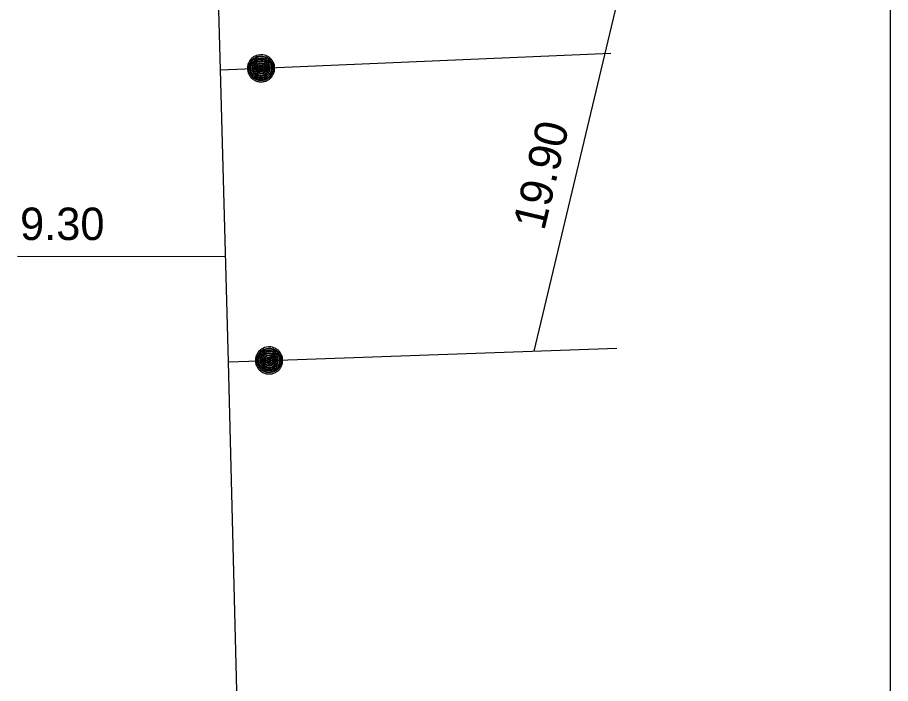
# Model space of a CAD drawing. Extents: x -820257 to -819974, y -1070894 to -1070484.
# Drawn here: x -820007.89 to -819975.6, y -1070794.86 to -1070770.22 of the extents above; entities that cross this region are included whole.
import ezdxf

# ---------------------------------------------------------------- set-up
doc = ezdxf.new("R2010")
doc.units = 0
for name, color, linetype in [('Default', 7, 'Continuous'), ('Oměrka vodovodu', 7, 'Continuous'), ('Oměrka-text', 7, 'Continuous'), ('Přípojka vodovodu', 7, 'Continuous'), ('Přípojkový uzávěr', 7, 'Continuous'), ('Roz-řad', 7, 'Continuous')]:
    doc.layers.add(name, color=color, linetype=linetype)

msp = doc.modelspace()

# ---------------------------------------------------------------- linework, layer by layer
at = {"layer": 'Default'}
msp.add_line((-819975.603, -1070893.932), (-819975.603, -1070484.403), dxfattribs=at)
at = {"layer": 'Oměrka vodovodu'}
for p, q in [((-819988.777, -1070782.56), (-819983.571, -1070760.651)), ((-820007.891, -1070779.053), (-820000.192, -1070779.056))]:
    msp.add_line(p, q, dxfattribs=at)
at = {"layer": 'Přípojka vodovodu'}
for points in [[(-820000.381, -1070772.161), (-819998.882, -1070772.096), (-819985.943, -1070771.539)], [(-820000.085, -1070782.958), (-819998.586, -1070782.905), (-819985.727, -1070782.453)]]:
    msp.add_lwpolyline(points, dxfattribs=at)
at = {"layer": 'Přípojkový uzávěr'}
for points in [[(-819998.904, -1070771.597), (-819998.778, -1070771.592), (-819998.656, -1070771.651), (-819998.534, -1070771.711), (-819998.461, -1070771.828), (-819998.388, -1070771.945), (-819998.382, -1070772.076), (-819998.377, -1070772.206), (-819998.438, -1070772.327), (-819998.498, -1070772.449), (-819998.615, -1070772.52), (-819998.731, -1070772.591), (-819998.861, -1070772.597), (-819998.99, -1070772.602), (-819999.112, -1070772.541), (-819999.234, -1070772.481), (-819999.305, -1070772.365), (-819999.376, -1070772.249), (-819999.381, -1070772.119), (-819999.387, -1070771.988), (-819999.325, -1070771.865), (-819999.263, -1070771.742), (-819999.147, -1070771.672), (-819999.03, -1070771.603), (-819998.904, -1070771.597)], [(-819998.902, -1070771.644), (-819999.016, -1070771.649), (-819999.122, -1070771.712), (-819999.228, -1070771.775), (-819999.284, -1070771.887), (-819999.34, -1070771.998), (-819999.335, -1070772.117), (-819999.33, -1070772.235), (-819999.265, -1070772.34), (-819999.201, -1070772.445), (-819999.091, -1070772.5), (-819998.98, -1070772.555), (-819998.863, -1070772.55), (-819998.745, -1070772.545), (-819998.639, -1070772.48), (-819998.534, -1070772.416), (-819998.479, -1070772.306), (-819998.424, -1070772.196), (-819998.429, -1070772.078), (-819998.434, -1070771.959), (-819998.501, -1070771.853), (-819998.567, -1070771.747), (-819998.677, -1070771.693), (-819998.788, -1070771.639), (-819998.902, -1070771.644)], [(-819998.9, -1070771.678), (-819998.795, -1070771.674), (-819998.693, -1070771.723), (-819998.59, -1070771.773), (-819998.529, -1070771.871), (-819998.468, -1070771.97), (-819998.463, -1070772.079), (-819998.459, -1070772.188), (-819998.509, -1070772.29), (-819998.56, -1070772.392), (-819998.658, -1070772.451), (-819998.755, -1070772.511), (-819998.864, -1070772.516), (-819998.973, -1070772.52), (-819999.075, -1070772.469), (-819999.177, -1070772.419), (-819999.237, -1070772.321), (-819999.296, -1070772.224), (-819999.301, -1070772.115), (-819999.305, -1070772.006), (-819999.253, -1070771.903), (-819999.202, -1070771.799), (-819999.104, -1070771.741), (-819999.006, -1070771.683), (-819998.9, -1070771.678)], [(-819998.899, -1070771.722), (-819999.055, -1070771.729), (-819999.159, -1070771.844), (-819999.263, -1070771.958), (-819999.257, -1070772.114), (-819999.25, -1070772.269), (-819999.135, -1070772.373), (-819999.021, -1070772.478), (-819998.867, -1070772.472), (-819998.711, -1070772.465), (-819998.606, -1070772.351), (-819998.501, -1070772.236), (-819998.507, -1070772.081), (-819998.514, -1070771.926), (-819998.628, -1070771.821), (-819998.742, -1070771.716), (-819998.899, -1070771.722)], [(-819998.897, -1070771.768), (-819998.76, -1070771.762), (-819998.661, -1070771.854), (-819998.561, -1070771.946), (-819998.555, -1070772.082), (-819998.549, -1070772.218), (-819998.641, -1070772.318), (-819998.733, -1070772.418), (-819998.869, -1070772.424), (-819999.005, -1070772.43), (-819999.105, -1070772.338), (-819999.205, -1070772.246), (-819999.211, -1070772.11), (-819999.217, -1070771.974), (-819999.125, -1070771.874), (-819999.034, -1070771.774), (-819998.897, -1070771.768)], [(-819998.895, -1070771.808), (-819999.015, -1070771.813), (-819999.096, -1070771.901), (-819999.176, -1070771.989), (-819999.171, -1070772.108), (-819999.166, -1070772.228), (-819999.078, -1070772.309), (-819998.991, -1070772.389), (-819998.871, -1070772.384), (-819998.751, -1070772.379), (-819998.67, -1070772.291), (-819998.59, -1070772.203), (-819998.595, -1070772.084), (-819998.6, -1070771.964), (-819998.687, -1070771.883), (-819998.775, -1070771.803), (-819998.895, -1070771.808)], [(-819998.893, -1070771.847), (-819998.788, -1070771.843), (-819998.713, -1070771.913), (-819998.637, -1070771.983), (-819998.632, -1070772.087), (-819998.628, -1070772.19), (-819998.698, -1070772.266), (-819998.768, -1070772.342), (-819998.872, -1070772.347), (-819998.975, -1070772.351), (-819999.051, -1070772.281), (-819999.127, -1070772.212), (-819999.132, -1070772.108), (-819999.136, -1070772.004), (-819999.067, -1070771.928), (-819998.998, -1070771.852), (-819998.893, -1070771.847)], [(-819998.891, -1070771.894), (-819998.976, -1070771.897), (-819999.032, -1070771.959), (-819999.089, -1070772.021), (-819999.085, -1070772.105), (-819999.082, -1070772.19), (-819999.02, -1070772.246), (-819998.958, -1070772.303), (-819998.874, -1070772.299), (-819998.79, -1070772.296), (-819998.733, -1070772.234), (-819998.676, -1070772.172), (-819998.68, -1070772.088), (-819998.683, -1070772.003), (-819998.745, -1070771.947), (-819998.807, -1070771.89), (-819998.891, -1070771.894)], [(-819998.89, -1070771.928), (-819998.819, -1070771.925), (-819998.768, -1070771.972), (-819998.717, -1070772.019), (-819998.714, -1070772.089), (-819998.711, -1070772.159), (-819998.758, -1070772.211), (-819998.805, -1070772.262), (-819998.875, -1070772.265), (-819998.945, -1070772.268), (-819998.997, -1070772.221), (-819999.048, -1070772.174), (-819999.051, -1070772.104), (-819999.054, -1070772.033), (-819999.007, -1070771.982), (-819998.96, -1070771.931), (-819998.89, -1070771.928)], [(-819998.888, -1070771.972), (-819998.94, -1070771.974), (-819998.974, -1070772.012), (-819999.009, -1070772.051), (-819999.007, -1070772.102), (-819999.005, -1070772.154), (-819998.966, -1070772.189), (-819998.928, -1070772.224), (-819998.877, -1070772.222), (-819998.825, -1070772.22), (-819998.79, -1070772.181), (-819998.755, -1070772.143), (-819998.757, -1070772.092), (-819998.759, -1070772.04), (-819998.797, -1070772.005), (-819998.835, -1070771.97), (-819998.888, -1070771.972)], [(-819998.886, -1070772.019), (-819998.853, -1070772.017), (-819998.829, -1070772.039), (-819998.806, -1070772.06), (-819998.804, -1070772.094), (-819998.803, -1070772.126), (-819998.824, -1070772.15), (-819998.846, -1070772.174), (-819998.879, -1070772.175), (-819998.911, -1070772.176), (-819998.935, -1070772.154), (-819998.959, -1070772.133), (-819998.961, -1070772.1), (-819998.962, -1070772.067), (-819998.94, -1070772.044), (-819998.918, -1070772.02), (-819998.886, -1070772.019)], [(-819998.884, -1070772.05), (-819998.904, -1070772.051), (-819998.917, -1070772.065), (-819998.93, -1070772.079), (-819998.929, -1070772.099), (-819998.928, -1070772.119), (-819998.914, -1070772.132), (-819998.9, -1070772.145), (-819998.88, -1070772.144), (-819998.86, -1070772.143), (-819998.848, -1070772.129), (-819998.835, -1070772.114), (-819998.836, -1070772.095), (-819998.836, -1070772.075), (-819998.85, -1070772.062), (-819998.864, -1070772.049), (-819998.884, -1070772.05)], [(-819998.604, -1070782.405), (-819998.478, -1070782.401), (-819998.356, -1070782.461), (-819998.234, -1070782.521), (-819998.163, -1070782.639), (-819998.091, -1070782.757), (-819998.086, -1070782.888), (-819998.082, -1070783.017), (-819998.143, -1070783.139), (-819998.205, -1070783.26), (-819998.322, -1070783.33), (-819998.439, -1070783.4), (-819998.569, -1070783.404), (-819998.698, -1070783.409), (-819998.819, -1070783.347), (-819998.941, -1070783.286), (-819999.011, -1070783.169), (-819999.081, -1070783.053), (-819999.086, -1070782.923), (-819999.09, -1070782.792), (-819999.027, -1070782.669), (-819998.964, -1070782.547), (-819998.847, -1070782.478), (-819998.73, -1070782.41), (-819998.604, -1070782.405)], [(-819998.602, -1070782.452), (-819998.716, -1070782.456), (-819998.823, -1070782.518), (-819998.929, -1070782.58), (-819998.986, -1070782.691), (-819999.043, -1070782.803), (-819999.039, -1070782.921), (-819999.035, -1070783.039), (-819998.971, -1070783.144), (-819998.908, -1070783.25), (-819998.798, -1070783.306), (-819998.688, -1070783.362), (-819998.57, -1070783.358), (-819998.452, -1070783.353), (-819998.346, -1070783.29), (-819998.24, -1070783.226), (-819998.185, -1070783.117), (-819998.129, -1070783.007), (-819998.133, -1070782.889), (-819998.137, -1070782.771), (-819998.203, -1070782.664), (-819998.268, -1070782.557), (-819998.378, -1070782.502), (-819998.488, -1070782.448), (-819998.602, -1070782.452)], [(-819998.601, -1070782.486), (-819998.495, -1070782.482), (-819998.394, -1070782.533), (-819998.292, -1070782.583), (-819998.231, -1070782.682), (-819998.171, -1070782.781), (-819998.167, -1070782.89), (-819998.163, -1070782.999), (-819998.215, -1070783.101), (-819998.266, -1070783.202), (-819998.364, -1070783.261), (-819998.462, -1070783.32), (-819998.572, -1070783.323), (-819998.68, -1070783.327), (-819998.782, -1070783.276), (-819998.884, -1070783.224), (-819998.942, -1070783.126), (-819999.001, -1070783.029), (-819999.005, -1070782.92), (-819999.008, -1070782.81), (-819998.956, -1070782.707), (-819998.903, -1070782.605), (-819998.805, -1070782.547), (-819998.707, -1070782.49), (-819998.601, -1070782.486)], [(-819998.6, -1070782.53), (-819998.756, -1070782.535), (-819998.861, -1070782.649), (-819998.966, -1070782.763), (-819998.961, -1070782.918), (-819998.955, -1070783.074), (-819998.842, -1070783.179), (-819998.728, -1070783.285), (-819998.574, -1070783.28), (-819998.418, -1070783.274), (-819998.312, -1070783.161), (-819998.206, -1070783.047), (-819998.211, -1070782.892), (-819998.217, -1070782.736), (-819998.33, -1070782.63), (-819998.442, -1070782.524), (-819998.6, -1070782.53)], [(-819998.598, -1070782.576), (-819998.461, -1070782.571), (-819998.363, -1070782.664), (-819998.264, -1070782.756), (-819998.259, -1070782.892), (-819998.254, -1070783.028), (-819998.347, -1070783.128), (-819998.439, -1070783.227), (-819998.575, -1070783.232), (-819998.712, -1070783.237), (-819998.811, -1070783.144), (-819998.91, -1070783.051), (-819998.915, -1070782.915), (-819998.92, -1070782.779), (-819998.827, -1070782.68), (-819998.735, -1070782.581), (-819998.598, -1070782.576)], [(-819998.597, -1070782.615), (-819998.717, -1070782.62), (-819998.798, -1070782.707), (-819998.879, -1070782.794), (-819998.875, -1070782.914), (-819998.871, -1070783.033), (-819998.784, -1070783.115), (-819998.697, -1070783.196), (-819998.577, -1070783.192), (-819998.457, -1070783.188), (-819998.376, -1070783.101), (-819998.294, -1070783.013), (-819998.299, -1070782.894), (-819998.303, -1070782.774), (-819998.39, -1070782.693), (-819998.477, -1070782.611), (-819998.597, -1070782.615)], [(-819998.595, -1070782.655), (-819998.49, -1070782.651), (-819998.415, -1070782.722), (-819998.34, -1070782.792), (-819998.336, -1070782.896), (-819998.332, -1070783), (-819998.403, -1070783.075), (-819998.474, -1070783.151), (-819998.578, -1070783.155), (-819998.681, -1070783.158), (-819998.756, -1070783.088), (-819998.832, -1070783.017), (-819998.836, -1070782.914), (-819998.839, -1070782.81), (-819998.769, -1070782.734), (-819998.7, -1070782.659), (-819998.595, -1070782.655)], [(-819998.594, -1070782.701), (-819998.678, -1070782.704), (-819998.735, -1070782.766), (-819998.792, -1070782.827), (-819998.789, -1070782.911), (-819998.786, -1070782.996), (-819998.725, -1070783.053), (-819998.664, -1070783.11), (-819998.579, -1070783.107), (-819998.495, -1070783.104), (-819998.438, -1070783.043), (-819998.38, -1070782.982), (-819998.383, -1070782.897), (-819998.386, -1070782.813), (-819998.448, -1070782.756), (-819998.509, -1070782.698), (-819998.594, -1070782.701)], [(-819998.592, -1070782.736), (-819998.522, -1070782.733), (-819998.471, -1070782.781), (-819998.421, -1070782.828), (-819998.418, -1070782.898), (-819998.416, -1070782.969), (-819998.463, -1070783.019), (-819998.511, -1070783.07), (-819998.58, -1070783.073), (-819998.651, -1070783.075), (-819998.702, -1070783.028), (-819998.752, -1070782.98), (-819998.755, -1070782.91), (-819998.757, -1070782.84), (-819998.71, -1070782.789), (-819998.663, -1070782.738), (-819998.592, -1070782.736)], [(-819998.591, -1070782.78), (-819998.642, -1070782.782), (-819998.678, -1070782.82), (-819998.713, -1070782.857), (-819998.711, -1070782.909), (-819998.709, -1070782.961), (-819998.671, -1070782.996), (-819998.633, -1070783.031), (-819998.582, -1070783.03), (-819998.53, -1070783.028), (-819998.494, -1070782.99), (-819998.459, -1070782.952), (-819998.461, -1070782.9), (-819998.463, -1070782.849), (-819998.5, -1070782.813), (-819998.538, -1070782.778), (-819998.591, -1070782.78)], [(-819998.589, -1070782.827), (-819998.556, -1070782.826), (-819998.533, -1070782.847), (-819998.509, -1070782.869), (-819998.508, -1070782.902), (-819998.507, -1070782.934), (-819998.529, -1070782.958), (-819998.55, -1070782.982), (-819998.584, -1070782.983), (-819998.616, -1070782.984), (-819998.64, -1070782.962), (-819998.663, -1070782.94), (-819998.664, -1070782.907), (-819998.666, -1070782.874), (-819998.643, -1070782.851), (-819998.621, -1070782.828), (-819998.589, -1070782.827)], [(-819998.588, -1070782.858), (-819998.608, -1070782.859), (-819998.621, -1070782.872), (-819998.634, -1070782.886), (-819998.633, -1070782.906), (-819998.633, -1070782.926), (-819998.618, -1070782.939), (-819998.604, -1070782.952), (-819998.585, -1070782.952), (-819998.565, -1070782.951), (-819998.552, -1070782.937), (-819998.539, -1070782.923), (-819998.54, -1070782.903), (-819998.54, -1070782.883), (-819998.554, -1070782.87), (-819998.568, -1070782.857), (-819998.588, -1070782.858)]]:
    msp.add_open_spline(points, degree=3, dxfattribs=at)
at = {"layer": 'Roz-řad'}
msp.add_lwpolyline([(-819998.171, -1070870.117), (-819998.405, -1070853.152), (-819998.628, -1070844.86), (-819999.183, -1070819.957), (-819999.443, -1070808.28), (-820000.085, -1070782.958), (-820000.381, -1070772.161), (-820000.485, -1070768.618)], dxfattribs=at)

# ---------------------------------------------------------------- texts
at = {"layer": 'Oměrka-text'}
for s, rotation, p in [('19.90', 76.6333, (-819988.411, -1070778.135)), (' 9.30', 359.9776, (-820008.241, -1070778.451))]:
    msp.add_text(s, height=1.2, rotation=rotation, dxfattribs=at).set_placement(p)

doc.saveas('drawing.dxf')
